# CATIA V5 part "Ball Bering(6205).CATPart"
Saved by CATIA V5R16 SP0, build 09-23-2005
Part number: Ball Bering(6205)
Bounding box of the stored display mesh (mm): x -25.983 to 25.983, y -7.5 to 7.5, z -26 to 26
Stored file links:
  C:\V5_education\CATIA Data\ASD\Power Transmission Gear Assembly\Assembly Data\Ball Bering(6205).CATPart
  C:\Program Files\Dassault Systemes\B20\win_b64\startup\materials\Catalog.CATMaterial
  D:\#10 Work\#01 CATIA Lecture Materials\#03 Bearing Template\#02 Document\Ball Bearing DesignTable.xls
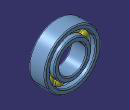
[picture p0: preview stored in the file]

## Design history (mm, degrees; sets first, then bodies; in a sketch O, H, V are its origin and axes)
External parameters (linked from other documents)
  External.D = 52 mm
  External.d = 25 mm
  External.B = 15 mm
  External.r = 0.975 mm
  External.s = 3.51 mm {= (External.D -External.d )*0.13}
  External.Z = 11 {= int((External.D + External.d ) / (External.s * 2) ) +1}
  `External.Bearing Number` = "6205"
Set1 "Reference Data"
  Point1 "Center Point": (0, 0, 0)
  Point2: (0, 0, 19.25 {= (External.D+External.d)/4}), relative to Point1
  Sphere1 "Ball": Center Point2, Radius 3.51 {= External.s}, Angle1 -45, Angle3 0, Angle4 180
Body1 "PartBody" (main body)
  Body2 "Body.1"
    Sketch1 on xy-plane, origin (0, 0, 0), H (1, 0, 0), V (0, 1, 0)
      axis line L1 (0, 0) -> (0, 87.7764)
      construction line L2 (19.25, 0) -> (19.25, 15.0879)
      point P2 (19.25, 0)
      line L3 (12.5, 7.5) -> (26, 7.5)
      line L4 (26, 7.5) -> (26, -7.5)
      line L5 (26, -7.5) -> (12.5, -7.5)
      line L6 (12.5, -7.5) -> (12.5, 7.5)
      distance L3 L5 = 15 {= External.B}
      distance L1 L6 = 12.5 {= External.d /2}
      distance L1 L4 = 26 {= External.D /2}
      vertical: L1 V, L2 V, L4 V, L6 V
      coincidence: P2 H
      horizontal: L3 H, L5 H
      symmetry: L6 L4 L2, L3 L5 H
    Shaft1: profile Sketch1, axis Sketch1.L1, angle 360
    Sketch2 on xy-plane, origin (0, 0, 0), H (1, 0, 0), V (0, 1, 0)
      axis line L1 (0, 0) -> (0, 17.8821)
      line L2 (17.225, 7.5) -> (21.275, 7.5)
      line L3 (21.275, 7.5) -> (21.275, 2.867)
      line L4 (21.275, -7.5) -> (17.225, -7.5)
      line L5 (17.225, -7.5) -> (17.225, -2.867)
      arc A1 centre (19.25, 0) radius 3.51 from (17.225, 2.867) to (17.225, -2.867) ccw
      point P6 (19.25, 0)
      construction line L6 (19.25, 0) -> (19.25, 7.5)
      point P7 (19.25, 7.5)
      point P8 (21.275, -2.867)
      line L7 (21.275, -2.867) -> (21.275, -7.5)
      point P10 (17.225, 2.867)
      line L8 (17.225, 2.867) -> (17.225, 7.5)
      arc A2 centre (19.25, 0) radius 3.51 from (21.275, -2.867) to (21.275, 2.867) ccw
      distance L5 L3 = 4.05 {= (External.D - External.d) * 0.15}
      radius A1 = 3.51 {= External.s}
      distance L2 L4 = 15 {= External.B}
      distance L6 L1 = 19.25 {= Point2.Z}
      vertical: L1 V, L3 V, L5 V, L6 V, L7 V, L8 V
      horizontal: L2 H, L4 H
      coincidence: P6 H, A1 P8, L3 L7, L5 P10, L5 L8, A1 A2
      midpoint: P7 L2
      symmetry: L5 L3 L6, L2 L4 H
    Groove1: profile Sketch2, axis Sketch2.L1, angle 360
    Fillet1: radius 0.975 {= External.r}, on face of Shaft1 from Sketch1.L4; edge [face of Shaft1 from Sketch1.L6 | face of Shaft1 from Sketch1.L5]; edge [face of Shaft1 from Sketch1.L3 | face of Shaft1 from Sketch1.L6]; edge [face of Groove1 from Sketch2.L7 | face of Shaft1 from Sketch1.L5]; edge [face of Shaft1 from Sketch1.L5 | face of Groove1 from Sketch2.L5]; edge [face of Shaft1 from Sketch1.L3 | face of Groove1 from Sketch2.L3]; edge [face of Groove1 from Sketch2.L8 | face of Shaft1 from Sketch1.L3]
  Assemble1: tool Body2
  Body3
    CloseSurface1: CloseElement Sphere1
    CircPattern1: of the body so far, instances 11 {= External.Z}, angular step 32.7273 {= 360.0*1 deg/CircPattern1.AngularNumber}, axis from zx-plane
  Assemble2: tool Body3
Relations
  rule:
    if `External.Bearing Number` =="6200"
    	{
    		External.D = 30mm
    		External.d = 10mm
    		External.B = 9mm
    		External.r = 0.61mm
    	}
    else if `External.Bearing Number` =="6201"
    	{
    		External.D = 32mm
    		External.d = 12mm
    		External.B = 10mm
    		External.r = 0.61mm
    	}
    else if `External.Bearing Number` =="6202"
    	{
    		External.D = 35mm
    		External.d = 15mm
    		External.B = 11mm
    		External.r = 0.61mm
    	}
    else if `External.Bearing Number` =="6203"
    	{
    		External.D = 40mm
    		External.d = 17mm
    		External.B = 12mm
    		External.r = 0.61mm
    	}
    else if `External.Bearing Number` =="6204"
    	{
    		External.D = 47mm
    		External.d = 20mm
    		External.B = 14mm
    		External.r = 0.975mm
    	}
    else if `External.Bearing Number` =="6205"
    	{
    		External.D = 52mm
    		External.d = 25mm
    		External.B = 15mm
    		External.r = 0.975mm
    	}
    else if `External.Bearing Number` =="6206"
    	{
    		External.D = 62mm
    		External.d = 30mm
    		External.B = 16mm
    		External.r = 0.975mm
    	}
    else if `External.Bearing Number` =="6207"
    	{
    		External.D = 72mm
    		External.d = 35mm
    		External.B = 17mm
    		External.r = 0.975mm
    	}
    else if `External.Bearing Number` =="6208"
    	{
    		External.D = 80mm
    		External.d = 40mm
    		External.B = 18mm
    		External.r = 0.975mm
    	}
    else if `External.Bearing Number` =="6209"
    	{
    		External.D = 85mm
    		External.d = 45mm
    		External.B = 19mm
    		External.r = 0.975mm
    	}
    else
    	{
    		External.D = 90mm
    		External.d = 50mm
    		External.B = 20mm
    		External.r = 0.975mm
    	}
  design table "Ball Bearing Design Table", configuration 1, drives `External.Bearing Number`, External.D, External.d, External.B, External.r (deactivated)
